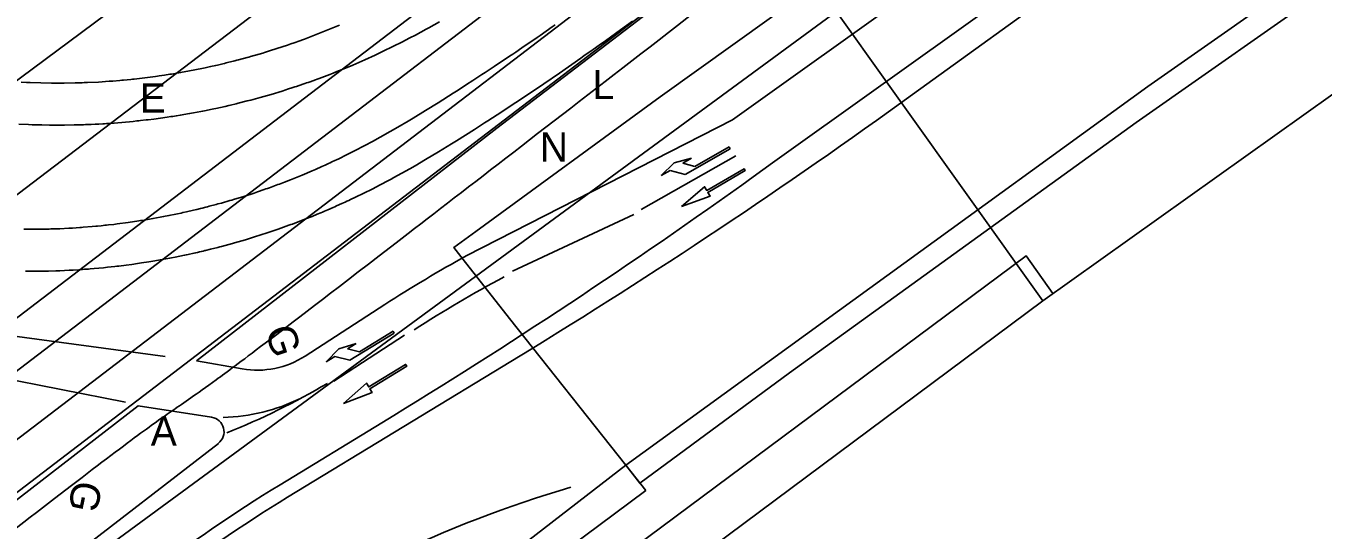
# Model space of a CAD drawing. Extents: x 81617 to 82144, y 454649 to 455150.
# Drawn here: x 81935.65 to 81979.96, y 454969.8 to 454987.03 of the extents above; entities that cross this region are included whole.
import ezdxf

# ---------------------------------------------------------------- set-up
doc = ezdxf.new("R2010")
doc.units = 0
for name, color, linetype in [('B-WE-OG-TOPOGRAFIE-G', 7, 'Continuous'), ('B-WE-VW-MARKERING-G', 7, 'Continuous'), ('N-OI-KL-VRI_KABELGEUL-G', 7, 'Continuous')]:
    doc.layers.add(name, color=color, linetype=linetype)

msp = doc.modelspace()

# ---------------------------------------------------------------- linework, layer by layer
at = {"layer": 'B-WE-OG-TOPOGRAFIE-G'}
for p, q in [((81962.08, 454989.284), (81970.379, 454977.638)), ((81950.705, 454979.183), (81959.785, 454983.825)), ((81952.17, 454977.038), (81950.581, 454979.048)), ((81947.904, 454977.511), (81945.182, 454975.749)), ((81956.136, 454972.02), (81952.17, 454977.038)), ((81944.586, 454970.925), (81952.527, 454975.762)), ((81944.326, 454971.352), (81947.804, 454973.47)), ((81942.218, 454972.767), (81935.772, 454967.788)), ((81956.136, 454972.02), (81928.665, 454950.799)), ((81956.823, 454971.151), (81956.136, 454972.02)), ((81952.992, 454968.309), (81956.823, 454971.151))]:
    msp.add_line(p, q, dxfattribs=at)
for points in [[(81959.785, 454983.825), (81978.143, 454996.941), (81996.774, 455009.764), (82016.278, 455022.758), (82037.965, 455036.748), (82038.034, 455036.785), (82041.792, 455039.152), (82061.121, 455051.062), (82076.512, 455060.199), (82092.497, 455069.379)], [(81960.485, 454981.872), (81961.152, 454982.351), (81979.261, 454995.289), (81997.857, 455008.089), (82017.331, 455021.062), (82038.916, 455034.987), (82038.973, 455035.017), (82042.795, 455037.425), (82062.097, 455049.318), (82077.455, 455058.435), (82093.547, 455067.677)], [(82094.196, 455067.034), (82080.353, 455059.107), (82061.604, 455047.995), (82058.217, 455045.922), (82040.23, 455034.796), (82020.805, 455022.33), (82020.067, 455021.852), (81999.057, 455007.868), (81989.298, 455001.207), (81971.359, 454988.622), (81965.928, 454984.683)], [(81873.49, 454927.861), (81874.235, 454928.464), (81874.684, 454928.824), (81874.834, 454928.943), (81875.133, 454929.183), (81876.035, 454929.897), (81876.336, 454930.134), (81876.944, 454930.61), (81877.553, 454931.084), (81877.859, 454931.32), (81878.164, 454931.557), (81879.083, 454932.264), (81879.697, 454932.734), (81880.618, 454933.44), (81881.483, 454934.1), (82053.484, 455065.539)], [(82052.863, 455062.717), (81907.219, 454951.42), (81881.918, 454932.086), (81881.368, 454931.665), (81879.897, 454930.54), (81879.014, 454929.861), (81878.133, 454929.178), (81876.818, 454928.147), (81876.529, 454927.916), (81876.383, 454927.802), (81875.945, 454927.452), (81875.222, 454926.872), (81874.931, 454926.636), (81874.646, 454926.404), (81874.501, 454926.287), (81873.923, 454925.815), (81873.138, 454925.168), (81872.64, 454924.754), (81871.896, 454924.132), (81871.4, 454923.716), (81870.675, 454923.104)], [(82053.734, 455061.577), (81908.09, 454950.28), (81882.79, 454930.946), (81882.24, 454930.525), (81880.77, 454929.401), (81879.891, 454928.725), (81879.015, 454928.046), (81877.708, 454927.021), (81877.419, 454926.791), (81877.274, 454926.677), (81876.842, 454926.332), (81876.122, 454925.754), (81875.835, 454925.522), (81875.549, 454925.289), (81875.405, 454925.173), (81874.834, 454924.706), (81874.053, 454924.062), (81873.558, 454923.651), (81872.817, 454923.032), (81872.324, 454922.618), (81871.758, 454922.14)], [(81950.581, 454979.048), (81950.258, 454979.457), (81951.016, 454980.007), (81957.307, 454984.609), (81976.332, 454998.23), (81995.586, 455011.524), (82010.894, 455021.673), (82036.711, 455038.408), (82036.761, 455038.448), (82038.729, 455039.685), (82059.085, 455052.226), (82059.468, 455052.453)], [(82045.659, 455031.568), (82023.867, 455017.635), (82003.98, 455004.472), (81992.321, 454996.518), (81980.684, 454988.403), (81980.535, 454988.615), (81973.576, 454983.735), (81961.735, 454975.174), (81956.622, 454971.406), (81956.136, 454972.02)], [(82022.537, 455018.09), (82001.572, 455004.136), (81991.859, 454997.506), (81973.972, 454984.959), (81956.136, 454972.02)], [(81996.533, 455017.836), (81976.69, 455002.613), (81951.736, 454983.533), (81941.467, 454975.587)], [(81935.606, 454951.727), (81935.945, 454951.99), (81970.379, 454977.638), (81981.277, 454985.41), (82010.63, 455005.695), (82021.766, 455012.972)], [(81901.778, 454951.416), (81947.621, 454986.447), (81958.806, 454994.995), (81973.12, 455005.933)], [(81942.829, 454984.371), (81942.892, 454984.386), (81943.207, 454984.466), (81943.27, 454984.483), (81943.333, 454984.499), (81943.647, 454984.584), (81944.022, 454984.692), (81944.396, 454984.805), (81944.52, 454984.845), (81944.582, 454984.864), (81944.768, 454984.924), (81944.829, 454984.945), (81944.891, 454984.965), (81945.107, 454985.038), (81945.168, 454985.06), (81945.23, 454985.081), (81945.291, 454985.103), (81945.353, 454985.124), (81945.536, 454985.19), (81945.597, 454985.213), (81945.658, 454985.235), (81946.024, 454985.373), (81946.145, 454985.421), (81946.266, 454985.468), (81946.326, 454985.493), (81946.447, 454985.541), (81946.807, 454985.691), (81947.225, 454985.873), (81947.58, 454986.035), (81947.734, 454986.107), (81947.802, 454986.14), (81947.829, 454986.152), (81948.206, 454986.336), (81948.486, 454986.477), (81948.764, 454986.621), (81948.949, 454986.718), (81949.316, 454986.916), (81949.407, 454986.967)], [(81945.161, 454986.581), (81945.62, 454986.756), (81945.677, 454986.779), (81945.734, 454986.801), (81945.905, 454986.87), (81945.962, 454986.894), (81946.019, 454986.917), (81946.359, 454987.06)], [(81953.729, 454987.068), (81953.625, 454986.996), (81953.419, 454986.851), (81953.211, 454986.708), (81953.108, 454986.636), (81952.588, 454986.28), (81952.379, 454986.138), (81952.274, 454986.068), (81952.17, 454985.997), (81951.646, 454985.647), (81951.33, 454985.439), (81951.225, 454985.369), (81951.014, 454985.231), (81950.908, 454985.163), (81950.697, 454985.025), (81950.41, 454984.84), (81950.24, 454984.731), (81949.728, 454984.407), (81949.3, 454984.141), (81948.87, 454983.88), (81948.698, 454983.777), (81948.352, 454983.574), (81948.092, 454983.424), (81947.743, 454983.228), (81947.481, 454983.084)], [(81956.371, 454987.197), (81955.958, 454986.896), (81955.439, 454986.521), (81955.231, 454986.373), (81955.023, 454986.224), (81954.709, 454986.003), (81954.605, 454985.929), (81953.87, 454985.418), (81953.342, 454985.057), (81952.812, 454984.7), (81952.386, 454984.416), (81951.745, 454983.995), (81951.423, 454983.786), (81951.315, 454983.717), (81950.969, 454983.494), (81950.358, 454983.109), (81950.183, 454983), (81949.742, 454982.73), (81949.297, 454982.464), (81948.938, 454982.255), (81948.757, 454982.152), (81948.485, 454981.999), (81948.211, 454981.848), (81948.119, 454981.798)], [(81949.407, 454986.967), (81949.771, 454987.169)], [(81939.284, 454985.209), (81939.345, 454985.215), (81939.711, 454985.257), (81940.076, 454985.305), (81940.137, 454985.314), (81940.198, 454985.322), (81940.38, 454985.349), (81940.441, 454985.359), (81940.502, 454985.368), (81940.562, 454985.378), (81940.623, 454985.387), (81940.744, 454985.407), (81940.926, 454985.438), (81941.228, 454985.493), (81941.65, 454985.576), (81941.77, 454985.602), (81941.951, 454985.64), (81942.13, 454985.681), (81942.19, 454985.694), (81942.37, 454985.736), (81942.429, 454985.751), (81942.489, 454985.765), (81942.728, 454985.824), (81942.787, 454985.84), (81942.847, 454985.855), (81942.906, 454985.871), (81943.203, 454985.95), (81943.262, 454985.967), (81943.321, 454985.983), (81943.616, 454986.068), (81943.734, 454986.104), (81943.793, 454986.121), (81943.969, 454986.175), (81944.437, 454986.326), (81944.549, 454986.364), (81944.582, 454986.376), (81944.64, 454986.395), (81944.698, 454986.416), (81944.814, 454986.456), (81944.872, 454986.477), (81944.93, 454986.497), (81945.161, 454986.581)], [(81935.48, 454985.108), (81935.664, 454985.099), (81935.725, 454985.097), (81935.787, 454985.094), (81936.155, 454985.082), (81936.524, 454985.076), (81936.647, 454985.076), (81936.708, 454985.075), (81936.77, 454985.075), (81936.831, 454985.076), (81936.954, 454985.076), (81937.322, 454985.082), (81937.445, 454985.086), (81937.507, 454985.087), (81937.568, 454985.089), (81937.629, 454985.092), (81937.752, 454985.096), (81938.12, 454985.114), (81938.488, 454985.138), (81938.549, 454985.143), (81938.611, 454985.147), (81938.856, 454985.167), (81938.917, 454985.173), (81938.978, 454985.178), (81939.223, 454985.202), (81939.284, 454985.209)], [(81936.446, 454983.642), (81936.511, 454983.641), (81936.641, 454983.641), (81936.706, 454983.64), (81936.771, 454983.64), (81936.836, 454983.641), (81936.966, 454983.641), (81937.292, 454983.646), (81937.357, 454983.648), (81937.422, 454983.649), (81937.617, 454983.655), (81937.682, 454983.658), (81937.747, 454983.66), (81937.812, 454983.663), (81937.877, 454983.665), (81938.007, 454983.671), (81938.072, 454983.675), (81938.137, 454983.678), (81938.267, 454983.686), (81938.332, 454983.689), (81938.397, 454983.694), (81938.526, 454983.702), (81938.916, 454983.732), (81939.304, 454983.768), (81939.434, 454983.782), (81939.498, 454983.788), (81939.563, 454983.795), (81939.757, 454983.818), (81939.822, 454983.825), (81940.015, 454983.849), (81940.467, 454983.911), (81940.595, 454983.931), (81940.66, 454983.94), (81940.724, 454983.95), (81940.788, 454983.961), (81940.917, 454983.981), (81941.237, 454984.036), (81941.301, 454984.048), (81941.365, 454984.059), (81941.621, 454984.107), (81941.685, 454984.12), (81941.749, 454984.132), (81942.004, 454984.184), (81942.067, 454984.198), (81942.131, 454984.211), (81942.449, 454984.281), (81942.576, 454984.311), (81942.639, 454984.325), (81942.829, 454984.371)], [(81935.405, 454983.675), (81935.73, 454983.66), (81935.86, 454983.656), (81935.925, 454983.653), (81935.99, 454983.651), (81936.055, 454983.65), (81936.186, 454983.646), (81936.446, 454983.642)], [(81947.481, 454983.084), (81947.217, 454982.943), (81946.864, 454982.759), (81946.776, 454982.714), (81946.509, 454982.581), (81946.42, 454982.538), (81946.331, 454982.494), (81946.258, 454982.46), (81946.203, 454982.433), (81946.092, 454982.381), (81946.036, 454982.354), (81945.98, 454982.329), (81945.868, 454982.277), (81945.812, 454982.252), (81945.756, 454982.226), (81945.532, 454982.126), (81945.475, 454982.102), (81945.419, 454982.077), (81945.079, 454981.933), (81944.966, 454981.887), (81944.909, 454981.863), (81944.794, 454981.817), (81944.737, 454981.795), (81944.68, 454981.772), (81944.48, 454981.694), (81944.365, 454981.65), (81944.307, 454981.629), (81944.25, 454981.607), (81944.134, 454981.565), (81944.019, 454981.522), (81943.961, 454981.502), (81943.903, 454981.481), (81943.845, 454981.461), (81943.787, 454981.44), (81943.554, 454981.36), (81943.496, 454981.341), (81943.438, 454981.321), (81943.087, 454981.207), (81942.734, 454981.099), (81942.675, 454981.082), (81942.616, 454981.064), (81942.321, 454980.979), (81942.202, 454980.947), (81942.143, 454980.93), (81941.905, 454980.867), (81941.845, 454980.852), (81941.786, 454980.836), (81941.667, 454980.806), (81941.607, 454980.792), (81941.488, 454980.762), (81941.368, 454980.734)], [(81948.119, 454981.798), (81947.935, 454981.699), (81947.842, 454981.651), (81947.75, 454981.602), (81947.471, 454981.458), (81947.19, 454981.317), (81946.907, 454981.179), (81946.731, 454981.095), (81946.672, 454981.068), (81946.613, 454981.04), (81946.553, 454981.013), (81946.494, 454980.985), (81946.435, 454980.958), (81946.257, 454980.878), (81946.197, 454980.852), (81946.138, 454980.825), (81945.959, 454980.747), (81945.899, 454980.722), (81945.839, 454980.696), (81945.779, 454980.671), (81945.719, 454980.645), (81945.599, 454980.595), (81945.418, 454980.522), (81945.358, 454980.497), (81945.115, 454980.401), (81944.75, 454980.262), (81944.689, 454980.24), (81944.628, 454980.217), (81944.26, 454980.085), (81943.89, 454979.959), (81943.456, 454979.819), (81943.145, 454979.724), (81942.77, 454979.615), (81942.707, 454979.598), (81942.33, 454979.495), (81942.267, 454979.479), (81942.204, 454979.462), (81941.951, 454979.398), (81941.776, 454979.356), (81941.762, 454979.352), (81941.698, 454979.337)], [(81941.368, 454980.734), (81941.128, 454980.678), (81941.008, 454980.652), (81940.948, 454980.638), (81940.828, 454980.612), (81940.768, 454980.6), (81940.708, 454980.587), (81940.587, 454980.563), (81940.527, 454980.55), (81940.467, 454980.538), (81940.406, 454980.527), (81940.346, 454980.515), (81940.285, 454980.504), (81940.225, 454980.492), (81939.983, 454980.448), (81939.922, 454980.438), (81939.862, 454980.427), (81939.619, 454980.387), (81939.558, 454980.378), (81939.498, 454980.368), (81939.133, 454980.314), (81938.767, 454980.266), (81938.706, 454980.259), (81938.645, 454980.251), (81938.462, 454980.23), (81938.4, 454980.224), (81938.339, 454980.217), (81938.278, 454980.211), (81938.217, 454980.204), (81938.095, 454980.192), (81938.033, 454980.187), (81937.911, 454980.175), (81937.604, 454980.15), (81937.543, 454980.146), (81937.482, 454980.141), (81937.236, 454980.125), (81937.175, 454980.122), (81937.114, 454980.118), (81936.806, 454980.103), (81936.684, 454980.099), (81936.622, 454980.096), (81936.499, 454980.092), (81936.438, 454980.091), (81936.376, 454980.089), (81936.315, 454980.088), (81936.253, 454980.086), (81936.069, 454980.083), (81936.007, 454980.083), (81935.946, 454980.082), (81935.577, 454980.082)], [(81941.698, 454979.337), (81941.635, 454979.322), (81941.571, 454979.308), (81941.508, 454979.293), (81941.444, 454979.279), (81941.381, 454979.264), (81941.19, 454979.222), (81941.126, 454979.209), (81941.063, 454979.195), (81940.744, 454979.13), (81940.616, 454979.106), (81940.552, 454979.093), (81940.488, 454979.081), (81940.424, 454979.07), (81940.296, 454979.046), (81939.975, 454978.991), (81939.91, 454978.981), (81939.846, 454978.97), (81939.589, 454978.93), (81939.524, 454978.921), (81939.46, 454978.911), (81939.266, 454978.884), (81939.073, 454978.858), (81938.814, 454978.826), (81938.749, 454978.819), (81938.685, 454978.811), (81938.426, 454978.783), (81938.361, 454978.777), (81938.296, 454978.77), (81937.972, 454978.74), (81937.842, 454978.73), (81937.777, 454978.724), (81937.712, 454978.719), (81937.647, 454978.715), (81937.582, 454978.71), (81937.517, 454978.706), (81937.452, 454978.701), (81937.257, 454978.689), (81937.192, 454978.686), (81937.127, 454978.682), (81936.802, 454978.667), (81936.737, 454978.665), (81936.672, 454978.662), (81936.412, 454978.654), (81936.281, 454978.652), (81936.216, 454978.65), (81936.086, 454978.648), (81936.021, 454978.648), (81935.956, 454978.647), (81935.63, 454978.647)], [(81953.679, 454967.17), (81969.81, 454979.18), (81970.723, 454977.883)], [(81941.467, 454975.587), (81943.034, 454975.313)], [(81939.478, 454974.048), (81923.575, 454961.742), (81923.877, 454961.345), (81919.157, 454957.774)], [(81941.989, 454973.657), (81939.478, 454974.048)]]:
    msp.add_lwpolyline(points, dxfattribs=at)
for centre, radius, start, end in [((81848.488, 455146.571), 200, 301.34548, 305.95874), ((81843.764, 455144.279), 200, 301.34548, 305.70434), ((81973.759, 454937.375), 47.743, 118.874, 122.7893), ((81943.552, 454978.268), 3, 260.0691, 302.9105), ((81941.912, 454973.163), 0.5, 307.6856, 81.1477), ((81970.596, 454928.223), 50.5, 121.3455, 127.6856), ((81970.596, 454928.223), 50, 121.3455, 127.6856)]:
    msp.add_arc(centre, radius, start, end, dxfattribs=at)
at = {"layer": 'B-WE-VW-MARKERING-G'}
for p, q in [((81930.414, 454977.529), (81947.033, 454990.169)), ((81939.522, 454988.277), (81930.537, 454981.632)), ((81958.493, 454982.229), (81959.665, 454982.898)), ((81959.665, 454982.898), (81959.702, 454982.833)), ((81959.902, 454982.594), (81956.659, 454980.756)), ((81957.792, 454982.347), (81958.387, 454982.514)), ((81958.387, 454982.514), (81958.084, 454982.34)), ((81959.702, 454982.833), (81958.161, 454981.953)), ((81957.345, 454981.919), (81957.792, 454982.347)), ((81957.649, 454982.092), (81957.345, 454981.919)), ((81958.161, 454981.953), (81957.649, 454982.092)), ((81958.084, 454982.34), (81958.493, 454982.229)), ((81956.414, 454980.587), (81952.266, 454978.647)), ((81940.399, 454975.738), (81934.739, 454976.5)), ((81948.583, 454976.462), (81946.162, 454974.895)), ((81948.229, 454976.532), (81946.713, 454975.609)), ((81947.037, 454975.894), (81948.19, 454976.596)), ((81948.19, 454976.596), (81948.229, 454976.532)), ((81945.899, 454975.552), (81946.334, 454975.992)), ((81946.334, 454975.992), (81946.924, 454976.176)), ((81946.924, 454976.176), (81946.625, 454975.994)), ((81946.625, 454975.994), (81947.037, 454975.894)), ((81946.198, 454975.734), (81945.899, 454975.552)), ((81946.713, 454975.609), (81946.198, 454975.734)), ((81939.05, 454974.173), (81933.256, 454975.312))]:
    msp.add_line(p, q, dxfattribs=at)
for points in [[(81958.036, 454980.859), (81959.015, 454981.213), (81958.94, 454981.343), (81960.214, 454982.086), (81960.176, 454982.151), (81958.902, 454981.408), (81958.827, 454981.537)], [(81946.499, 454974.133), (81947.472, 454974.506), (81947.394, 454974.634), (81948.654, 454975.401), (81948.615, 454975.465), (81947.355, 454974.698), (81947.277, 454974.826)]]:
    msp.add_lwpolyline(points, close=True, dxfattribs=at)
for centre, radius, start, end in [((81971.208, 454942.281), 40.965, 117.9977, 122.9732), ((81933.028, 454996.702), 25.41, 291.9051, 300.5451), ((81942.227, 454979.985), 6.334, 271.3716, 296.1985), ((81965.713, 454932.156), 40.752, 106.3244, 125.1961)]:
    msp.add_arc(centre, radius, start, end, dxfattribs=at)
at = {"layer": 'N-OI-KL-VRI_KABELGEUL-G'}
msp.add_lwpolyline([(81969.078, 454991.751), (81925.426, 454959.701)], dxfattribs=at)
msp.add_open_spline([(81966.954, 454994.044), (81954.516, 454984.42), (81942.079, 454974.796), (81941.008, 454974.125), (81939.937, 454973.455), (81933.631, 454968.575), (81927.325, 454963.696), (81926.798, 454963.288), (81926.621, 454962.646), (81926.355, 454961.682), (81926.09, 454960.718), (81925.901, 454960.035), (81925.325, 454959.623), (81922.434, 454957.557), (81919.543, 454955.49), (81917.87, 454954.23), (81916.197, 454952.97), (81913.406, 454950.849), (81910.615, 454948.728), (81908.564, 454947.145), (81906.513, 454945.562), (81905.944, 454945.123), (81905.225, 454945.147), (81904.815, 454945.16), (81904.405, 454945.174), (81903.693, 454945.197), (81903.126, 454944.765), (81893.683, 454937.565), (81884.239, 454930.365), (81883.469, 454929.731), (81882.698, 454929.096), (81879.285, 454926.178), (81875.872, 454923.259), (81872.421, 454920.321), (81868.97, 454917.382), (81867.082, 454915.724), (81865.195, 454914.067), (81863.45, 454912.271), (81861.704, 454910.475), (81860.838, 454909.482), (81859.972, 454908.49), (81859.86, 454908.361), (81859.97, 454908.23), (81860.094, 454908.077), (81860.218, 454907.925), (81863.368, 454903.762), (81866.518, 454899.599), (81866.598, 454899.497), (81866.679, 454899.395)], degree=4, dxfattribs=at)

# ---------------------------------------------------------------- texts
at = {"layer": 'B-WE-OG-TOPOGRAFIE-G'}
for s, p in [('L', (81955.003, 454984.529)), ('E', (81939.531, 454984.069)), ('N', (81953.198, 454982.396)), ('A', (81939.908, 454972.686))]:
    msp.add_text(s, height=1, dxfattribs=at).set_placement(p)
for rotation, p in [(288.0262, (81943.803, 454976.619)), (258.1169, (81937.288, 454971.549))]:
    msp.add_text('G', height=1, rotation=rotation, dxfattribs=at).set_placement(p)

doc.saveas('drawing.dxf')
